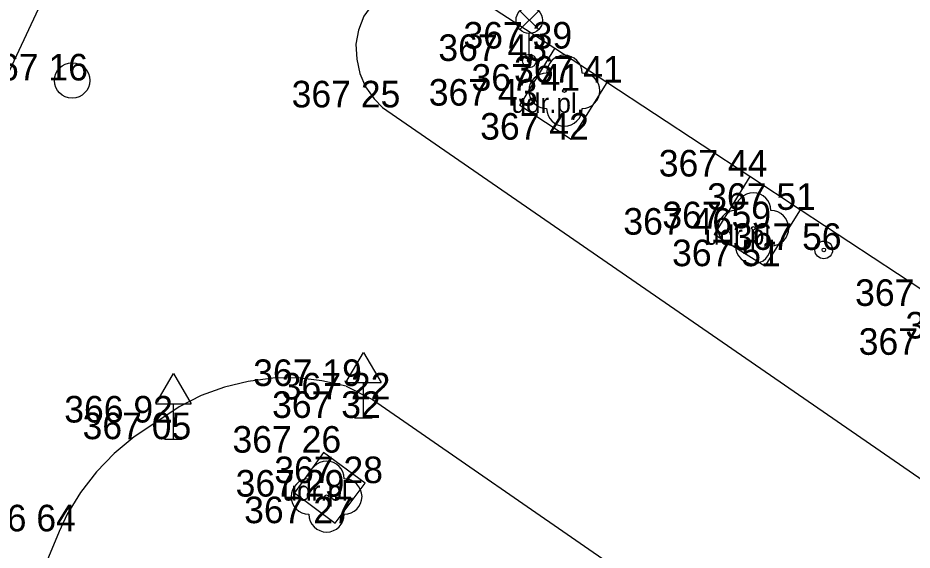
# Model space of a CAD drawing. Extents: x -688316 to -688024, y -973785 to -973591.
# Drawn here: x -688175.42 to -688150.19, y -973654.61 to -973639.59 of the extents above; entities that cross this region are included whole.
import ezdxf

# ---------------------------------------------------------------- set-up
doc = ezdxf.new("R2010")
doc.units = 0
for name, color, linetype in [('Vrstva 10', 7, 'Continuous'), ('Vrstva 1_elektro CEZ', 7, 'Continuous'), ('Vrstva 22', 7, 'Continuous'), ('Vrstva 25', 7, 'Continuous'), ('Vrstva 27', 7, 'Continuous'), ('Vrstva 3', 7, 'Continuous'), ('Vrstva 33', 7, 'Continuous'), ('Vrstva 34', 7, 'Continuous'), ('Vrstva 40', 7, 'Continuous')]:
    doc.layers.add(name, color=color, linetype=linetype)

# ---------------------------------------------------------------- blocks, each defined once
blk = doc.blocks.new('DZ')
at = {"layer": 'Vrstva 34'}
for p, q in [((-5, 10), (0, 18.5)), ((0, 18.5), (5, 10)), ((-5, 10), (5, 10)), ((0, 0), (0, 10)), ((-2.49, 0), (2.49, 0))]:
    blk.add_line(p, q, dxfattribs=at)
blk = doc.blocks.new('SAK')
at = {"layer": 'Vrstva 27'}
blk.add_circle((0, 0), 5, dxfattribs=at)
blk = doc.blocks.new('ZKUDR0')
at = {"layer": 'Vrstva 40'}
blk.add_text('udr.pl.', height=5.5, dxfattribs=at).set_placement((-11.71, -3.04))
blk = doc.blocks.new('STL')
at = {"layer": 'Vrstva 22'}
blk.add_circle((0, 0), 0.5, dxfattribs=at)
for centre, start, end in [((0, 5), 0, 180), ((-5, 0), 90, 270), ((5, 0), 270, 90), ((0, -5), 180, 0)]:
    blk.add_arc(centre, 5, start, end, dxfattribs=at)
blk = doc.blocks.new('SPMR')
at = {"layer": 'Vrstva 25'}
for radius in [2.5, 0.5]:
    blk.add_circle((0, 0), radius, dxfattribs=at)
blk = doc.blocks.new('LA')
at = {"layer": 'Vrstva 33'}
for p, q in [((-2.65, 14.15), (2.65, 8.85)), ((-2.65, 8.85), (2.65, 14.15)), ((0, 0), (0, 7.75))]:
    blk.add_line(p, q, dxfattribs=at)
for centre, radius in [((0, 11.5), 3.75), ((0, 0), 1.9), ((0, 0), 0.5)]:
    blk.add_circle(centre, radius, dxfattribs=at)

msp = doc.modelspace()

# ---------------------------------------------------------------- linework, layer by layer
at = {"layer": 'Vrstva 10'}
for p, q in [((-688161.26, -973642.07), (-688160.27, -973640.46)), ((-688158.8, -973641.42), (-688159.81, -973643.03)), ((-688165.13, -973642.12), (-688147.27, -973654.45)), ((-688159.81, -973643.03), (-688161.26, -973642.07)), ((-688154.77, -973644.07), (-688155.77, -973645.71)), ((-688153.35, -973645.01), (-688154.34, -973646.6)), ((-688154.34, -973646.6), (-688155.77, -973645.71)), ((-688166.16, -973649.98), (-688165.41, -973650.36)), ((-688165.41, -973650.36), (-688150.45, -973660.71))]:
    msp.add_line(p, q, dxfattribs=at)
for points in [[(-688163.16, -973638.65), (-688163.56, -973638.56), (-688163.97, -973638.54), (-688164.38, -973638.61), (-688164.77, -973638.75), (-688165.12, -973638.96), (-688165.43, -973639.24), (-688165.66, -973639.55), (-688165.81, -973639.94), (-688165.88, -973640.34), (-688165.86, -973640.76), (-688165.77, -973641.16), (-688165.61, -973641.54), (-688165.37, -973641.88), (-688165.13, -973642.12)], [(-688154.77, -973644.07), (-688158.8, -973641.42), (-688160.27, -973640.46), (-688162.78, -973638.82), (-688163.16, -973638.65)], [(-688149.23, -973647.72), (-688153.35, -973645.01), (-688154.77, -973644.07)], [(-688166.16, -973649.98), (-688166.84, -973649.83), (-688167.53, -973649.75), (-688168.23, -973649.76), (-688168.92, -973649.85), (-688169.59, -973650.01), (-688170.25, -973650.25), (-688170.87, -973650.57), (-688171.53, -973651.01), (-688172.14, -973651.41), (-688172.7, -973651.88), (-688173.2, -973652.4), (-688173.65, -973652.98), (-688174.03, -973653.6), (-688174.26, -973654.08)], [(-688165.62, -973652.72), (-688166.8, -973651.86), (-688167.62, -973652.99), (-688166.47, -973653.85), (-688165.62, -973652.72)], [(-688174.26, -973654.08), (-688174.56, -973654.81), (-688174.78, -973655.57), (-688174.93, -973656.35), (-688174.99, -973657.14), (-688174.98, -973657.93), (-688174.88, -973658.72), (-688174.71, -973659.49), (-688174.5, -973660.13)]]:
    msp.add_lwpolyline(points, dxfattribs=at)
at = {"layer": 'Vrstva 1_elektro CEZ'}
msp.add_lwpolyline([(-688190.282, -973658.121), (-688190.282, -973658.255), (-688190.094, -973658.256), (-688190.531, -973658.736), (-688188.15, -973660.224), (-688187.569, -973659.901), (-688184.139, -973653.841), (-688183.153, -973652.126), (-688176.422, -973642.693), (-688173.607, -973636.693), (-688162.702, -973616.499), (-688163.01, -973615.648), (-688168.054, -973613.093), (-688168.316, -973613.534), (-688168.345, -973613.555), (-688168.465, -973613.555), (-688168.465, -973613.42)], dxfattribs=at)

# ---------------------------------------------------------------- block references
at = {"layer": 'Vrstva 22', "xscale": 0.1, "yscale": 0.10000000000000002}
for p in [(-688160, -973641.65), (-688154.67, -973645.53), (-688166.71, -973653.1)]:
    msp.add_blockref('STL', p, dxfattribs=at)
at = {"layer": 'Vrstva 25', "xscale": 0.1, "yscale": 0.10000000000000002}
msp.add_blockref('SPMR', (-688152.68, -973646.14), dxfattribs=at)
at = {"layer": 'Vrstva 27', "xscale": 0.1, "yscale": 0.10000000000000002}
msp.add_blockref('SAK', (-688173.89, -973641.36), dxfattribs=at)
at = {"layer": 'Vrstva 33', "xscale": 0.1, "yscale": 0.10000000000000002}
msp.add_blockref('LA', (-688160.99, -973640.81), dxfattribs=at)
at = {"layer": 'Vrstva 34', "xscale": 0.1, "yscale": 0.10000000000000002}
for p in [(-688165.67, -973650.88), (-688165.67, -973650.88), (-688165.67, -973650.88), (-688165.67, -973650.88), (-688171.03, -973651.48), (-688171.03, -973651.48), (-688171.03, -973651.48), (-688171.03, -973651.48)]:
    msp.add_blockref('DZ', p, dxfattribs=at)
at = {"layer": 'Vrstva 40', "xscale": 0.1, "yscale": 0.10000000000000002}
for p in [(-688160.32, -973641.97), (-688154.86, -973645.69), (-688166.78, -973652.91)]:
    msp.add_blockref('ZKUDR0', p, dxfattribs=at)

# ---------------------------------------------------------------- texts
at = {"layer": 'Vrstva 3'}
for s, p in [('367 39 ', (-688162.848, -973640.46)), ('367 39 ', (-688162.848, -973640.46)), ('367 39 ', (-688162.848, -973640.46)), ('367 39 ', (-688162.848, -973640.46)), ('367 39 ', (-688162.848, -973640.46)), ('367 39 ', (-688162.848, -973640.46)), ('367 39 ', (-688162.848, -973640.46)), ('367 43 ', (-688163.556, -973640.81)), ('367 43 ', (-688163.556, -973640.81)), ('367 43 ', (-688163.556, -973640.81)), ('367 43 ', (-688163.556, -973640.81)), ('367 43 ', (-688163.556, -973640.81)), ('367 43 ', (-688163.556, -973640.81)), ('367 43 ', (-688163.556, -973640.81)), ('367 16 ', (-688176.511, -973641.36)), ('367 16 ', (-688176.511, -973641.36)), ('367 16 ', (-688176.511, -973641.36)), ('367 16 ', (-688176.511, -973641.36)), ('367 16 ', (-688176.511, -973641.36)), ('367 16 ', (-688176.511, -973641.36)), ('367 16 ', (-688176.511, -973641.36)), ('367 41 ', (-688161.421, -973641.42)), ('367 41 ', (-688161.421, -973641.42)), ('367 41 ', (-688161.421, -973641.42)), ('367 41 ', (-688161.421, -973641.42)), ('367 41 ', (-688161.421, -973641.42)), ('367 41 ', (-688161.421, -973641.42)), ('367 41 ', (-688161.421, -973641.42)), ('367 41 ', (-688162.621, -973641.65)), ('367 41 ', (-688162.621, -973641.65)), ('367 41 ', (-688162.621, -973641.65)), ('367 41 ', (-688162.621, -973641.65)), ('367 41 ', (-688162.621, -973641.65)), ('367 41 ', (-688162.621, -973641.65)), ('367 41 ', (-688162.621, -973641.65)), ('367 25 ', (-688167.696, -973642.12)), ('367 25 ', (-688167.696, -973642.12)), ('367 25 ', (-688167.696, -973642.12)), ('367 25 ', (-688167.696, -973642.12)), ('367 25 ', (-688167.696, -973642.12)), ('367 25 ', (-688167.696, -973642.12)), ('367 25 ', (-688167.696, -973642.12)), ('367 43 ', (-688163.826, -973642.07)), ('367 43 ', (-688163.826, -973642.07)), ('367 43 ', (-688163.826, -973642.07)), ('367 43 ', (-688163.826, -973642.07)), ('367 43 ', (-688163.826, -973642.07)), ('367 43 ', (-688163.826, -973642.07)), ('367 43 ', (-688163.826, -973642.07)), ('367 42 ', (-688162.376, -973643.03)), ('367 42 ', (-688162.376, -973643.03)), ('367 42 ', (-688162.376, -973643.03)), ('367 42 ', (-688162.376, -973643.03)), ('367 42 ', (-688162.376, -973643.03)), ('367 42 ', (-688162.376, -973643.03)), ('367 42 ', (-688162.376, -973643.03)), ('367 44 ', (-688157.336, -973644.07)), ('367 44 ', (-688157.336, -973644.07)), ('367 44 ', (-688157.336, -973644.07)), ('367 44 ', (-688157.336, -973644.07)), ('367 44 ', (-688157.336, -973644.07)), ('367 44 ', (-688157.336, -973644.07)), ('367 44 ', (-688157.336, -973644.07)), ('367 51 ', (-688155.971, -973645.01)), ('367 51 ', (-688155.971, -973645.01)), ('367 51 ', (-688155.971, -973645.01)), ('367 51 ', (-688155.971, -973645.01)), ('367 51 ', (-688155.971, -973645.01)), ('367 51 ', (-688155.971, -973645.01)), ('367 51 ', (-688155.971, -973645.01)), ('367 59 ', (-688157.236, -973645.53)), ('367 59 ', (-688157.236, -973645.53)), ('367 59 ', (-688157.236, -973645.53)), ('367 59 ', (-688157.236, -973645.53)), ('367 59 ', (-688157.236, -973645.53)), ('367 59 ', (-688157.236, -973645.53)), ('367 59 ', (-688157.236, -973645.53)), ('367 46 ', (-688158.336, -973645.71)), ('367 46 ', (-688158.336, -973645.71)), ('367 46 ', (-688158.336, -973645.71)), ('367 46 ', (-688158.336, -973645.71)), ('367 46 ', (-688158.336, -973645.71)), ('367 46 ', (-688158.336, -973645.71)), ('367 46 ', (-688158.336, -973645.71)), ('367 56 ', (-688155.246, -973646.14)), ('367 56 ', (-688155.246, -973646.14)), ('367 56 ', (-688155.246, -973646.14)), ('367 56 ', (-688155.246, -973646.14)), ('367 56 ', (-688155.246, -973646.14)), ('367 56 ', (-688155.246, -973646.14)), ('367 56 ', (-688155.246, -973646.14)), ('367 51 ', (-688156.961, -973646.6)), ('367 51 ', (-688156.961, -973646.6)), ('367 51 ', (-688156.961, -973646.6)), ('367 51 ', (-688156.961, -973646.6)), ('367 51 ', (-688156.961, -973646.6)), ('367 51 ', (-688156.961, -973646.6)), ('367 51 ', (-688156.961, -973646.6)), ('367 54 ', (-688151.796, -973647.72)), ('367 54 ', (-688151.796, -973647.72)), ('367 54 ', (-688151.796, -973647.72)), ('367 54 ', (-688151.796, -973647.72)), ('367 54 ', (-688151.796, -973647.72)), ('367 54 ', (-688151.796, -973647.72)), ('367 54 ', (-688151.796, -973647.72)), ('367 56 ', (-688150.376, -973648.64)), ('367 56 ', (-688150.376, -973648.64)), ('367 56 ', (-688150.376, -973648.64)), ('367 56 ', (-688150.376, -973648.64)), ('367 56 ', (-688150.376, -973648.64)), ('367 56 ', (-688150.376, -973648.64)), ('367 56 ', (-688150.376, -973648.64)), ('367 63 ', (-688151.695, -973649.1)), ('367 63 ', (-688151.695, -973649.1)), ('367 63 ', (-688151.695, -973649.1)), ('367 63 ', (-688151.695, -973649.1)), ('367 63 ', (-688151.695, -973649.1)), ('367 63 ', (-688151.695, -973649.1)), ('367 63 ', (-688151.695, -973649.1)), ('367 19 ', (-688168.781, -973649.98)), ('367 19 ', (-688168.781, -973649.98)), ('367 19 ', (-688168.781, -973649.98)), ('367 19 ', (-688168.781, -973649.98)), ('367 19 ', (-688168.781, -973649.98)), ('367 19 ', (-688168.781, -973649.98)), ('367 19 ', (-688168.781, -973649.98)), ('367 22 ', (-688167.976, -973650.36)), ('367 22 ', (-688167.976, -973650.36)), ('367 22 ', (-688167.976, -973650.36)), ('367 22 ', (-688167.976, -973650.36)), ('367 22 ', (-688167.976, -973650.36)), ('367 22 ', (-688167.976, -973650.36)), ('367 22 ', (-688167.976, -973650.36)), ('367 32 ', (-688168.248, -973650.88)), ('367 32 ', (-688168.248, -973650.88)), ('367 32 ', (-688168.248, -973650.88)), ('367 32 ', (-688168.248, -973650.88)), ('367 32 ', (-688168.248, -973650.88)), ('367 32 ', (-688168.248, -973650.88)), ('367 32 ', (-688168.248, -973650.88)), ('366 92 ', (-688174.113, -973651.01)), ('366 92 ', (-688174.113, -973651.01)), ('366 92 ', (-688174.113, -973651.01)), ('366 92 ', (-688174.113, -973651.01)), ('366 92 ', (-688174.113, -973651.01)), ('366 92 ', (-688174.113, -973651.01)), ('366 92 ', (-688174.113, -973651.01)), ('367 05 ', (-688173.596, -973651.48)), ('367 05 ', (-688173.596, -973651.48)), ('367 05 ', (-688173.596, -973651.48)), ('367 05 ', (-688173.596, -973651.48)), ('367 05 ', (-688173.596, -973651.48)), ('367 05 ', (-688173.596, -973651.48)), ('367 05 ', (-688173.596, -973651.48)), ('367 26 ', (-688169.366, -973651.86)), ('367 26 ', (-688169.366, -973651.86)), ('367 26 ', (-688169.366, -973651.86)), ('367 26 ', (-688169.366, -973651.86)), ('367 26 ', (-688169.366, -973651.86)), ('367 26 ', (-688169.366, -973651.86)), ('367 26 ', (-688169.366, -973651.86)), ('367 28 ', (-688168.186, -973652.72)), ('367 28 ', (-688168.186, -973652.72)), ('367 28 ', (-688168.186, -973652.72)), ('367 28 ', (-688168.186, -973652.72)), ('367 28 ', (-688168.186, -973652.72)), ('367 28 ', (-688168.186, -973652.72)), ('367 28 ', (-688168.186, -973652.72)), ('367 29 ', (-688169.276, -973653.1)), ('367 29 ', (-688169.276, -973653.1)), ('367 29 ', (-688169.276, -973653.1)), ('367 29 ', (-688169.276, -973653.1)), ('367 29 ', (-688169.276, -973653.1)), ('367 29 ', (-688169.276, -973653.1)), ('367 29 ', (-688169.276, -973653.1)), ('367 27 ', (-688169.036, -973653.85)), ('367 27 ', (-688169.036, -973653.85)), ('367 27 ', (-688169.036, -973653.85)), ('367 27 ', (-688169.036, -973653.85)), ('367 27 ', (-688169.036, -973653.85)), ('367 27 ', (-688169.036, -973653.85)), ('367 27 ', (-688169.036, -973653.85)), ('366 64 ', (-688176.852, -973654.08)), ('366 64 ', (-688176.852, -973654.08)), ('366 64 ', (-688176.852, -973654.08)), ('366 64 ', (-688176.852, -973654.08)), ('366 64 ', (-688176.852, -973654.08)), ('366 64 ', (-688176.852, -973654.08)), ('366 64 ', (-688176.852, -973654.08))]:
    msp.add_text(s, height=0.75, dxfattribs=at).set_placement(p)

doc.saveas('drawing.dxf')
